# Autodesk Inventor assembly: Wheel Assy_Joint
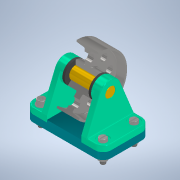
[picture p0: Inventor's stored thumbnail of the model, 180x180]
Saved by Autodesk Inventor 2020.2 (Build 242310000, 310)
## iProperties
Created: 2020-01
Part Number: Wheel Assy_Joint
Document SubType Name: Assembly
Designer: thira
Mass: 2271.79 g
Surface Area: 1143.13 cm^2
Volume: 405.195 cm^3
Density: 5.60665 g/cm^3
Author: thira
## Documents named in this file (11)
- C:\Users\thira\OneDrive\เดสก์ท็อป\INV-01 Intro to Modeling_2020\Wheel Assem Final V1\Wheel Assy_Joint.iam
- C:\Users\thira\OneDrive\เดสก์ท็อป\INV-01 Intro to Modeling_2020\Wheel Assem Final V1\Plate V1.ipt
- C:\Users\thira\OneDrive\เดสก์ท็อป\INV-01 Intro to Modeling_2020\Wheel Assem Final V1\Shaft V1.ipt
- C:\Users\thira\OneDrive\เดสก์ท็อป\INV-01 Intro to Modeling_2020\Wheel Assem Final V1\Support Wheel V1.ipt
- C:\Users\thira\OneDrive\เดสก์ท็อป\INV-01 Intro to Modeling_2020\Wheel Assem Final V1\Wheel V1.ipt
- C:\Users\thira\OneDrive\เดสก์ท็อป\INV-01 Intro to Modeling_2020\Wheel Assem Final V1\Seal.ipt
- C:\Users\thira\OneDrive\เอกสาร\Inventor\Content Center Files\R2020\en-US\ISO 1207(2)\ISO 1207 - M8 x 35.ipt
- C:\Users\thira\OneDrive\เอกสาร\Inventor\Content Center Files\R2020\en-US\ISO 7089\ISO 7089 - 10 - 140 HV(1).ipt
- C:\Users\thira\OneDrive\เอกสาร\Inventor\Content Center Files\R2020\en-US\ISO 4032(2)\ISO 4032 - M8 - ISO.ipt
- C:\Users\thira\OneDrive\เดสก์ท็อป\INV-01 Intro to Modeling_2020\Wheel Assem Final V1\Wheel Assy_Joint\Design Accelerator\Bolted Connection1.iam
- C:\Users\thira\OneDrive\เดสก์ท็อป\INV-01 Intro to Modeling_2020\Wheel Assem Final V1\Wheel Assy_Joint\Design Accelerator\Bolted Connection2.iam
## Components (17 placed, 9 different names)
1. Plate V1:1 — Rigid:1, Mate:1, Flush:1, Flush:2, Angle:1
2. Shaft V1:1 — Cylindrical:1, Planar:1, Cylindrical:2, Planar:2, Mate:2, Rotational:1
3. Support Wheel V1:1 — Rigid:1, Cylindrical:1, Planar:1, Flush:3, Flush:4, Mate:12, Mate:13, Mate:14, Mate:15
4. Wheel V1:1 — Cylindrical:2, Planar:2, Angle:1, Rotational:1
5. Support Wheel V1:2 — Mate:1, Flush:1, Flush:2, Mate:3
6. Seal:1 — Flush:3, Flush:4
7. Seal:2 — Mate:2, Mate:3
8. ISO 1207 M8 x 35:1
9. ISO 1207 M8 x 35:2
10. ISO 7089 10:1 — Mate:11
11. ISO 7089 10:2
12. ISO 7089 10:3 — Mate:9
13. ISO 7089 10:4
14. ISO 4032 M8:1 — Mate:9
15. ISO 4032 M8:2 — Mate:11
16. Bolted Connection:1 [sub-assembly] — Mate:12, Mate:13
17. Bolted Connection:2 [sub-assembly] — Mate:14, Mate:15
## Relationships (20: Mate 9, Flush 4, CylindricalJoint 2, PlanarJoint 2, WeldJoint 1, Angle 1, RevoluteJoint 1)
- Rigid:1 [WeldJoint]: Plate V1:1 ↔ Support Wheel V1:1
- Mate:1: Plate V1:1 ↔ Support Wheel V1:2
- Flush:1: Plate V1:1 ↔ Support Wheel V1:2
- Flush:2: Plate V1:1 ↔ Support Wheel V1:2
- Cylindrical:1: Shaft V1:1 ↔ Support Wheel V1:1
- Planar:1: Shaft V1:1 ↔ Support Wheel V1:1
- Cylindrical:2: Shaft V1:1 ↔ Wheel V1:1
- Planar:2: Shaft V1:1 ↔ Wheel V1:1
- Flush:3: Support Wheel V1:1 ↔ Seal:1
- Flush:4: Support Wheel V1:1 ↔ Seal:1
- Mate:2: Shaft V1:1 ↔ Seal:2
- Mate:3: Support Wheel V1:2 ↔ Seal:2
- Angle:1: Plate V1:1 ↔ Wheel V1:1
- Rotational:1 [RevoluteJoint]: Shaft V1:1 ↔ Wheel V1:1
- Mate:9: ISO 7089 10:3 ↔ ISO 4032 M8:1
- Mate:11: ISO 7089 10:1 ↔ ISO 4032 M8:2
- Mate:12: Support Wheel V1:1 ↔ Bolted Connection:1
- Mate:13: Support Wheel V1:1 ↔ Bolted Connection:1
- Mate:14: Support Wheel V1:1 ↔ Bolted Connection:2
- Mate:15: Support Wheel V1:1 ↔ Bolted Connection:2
